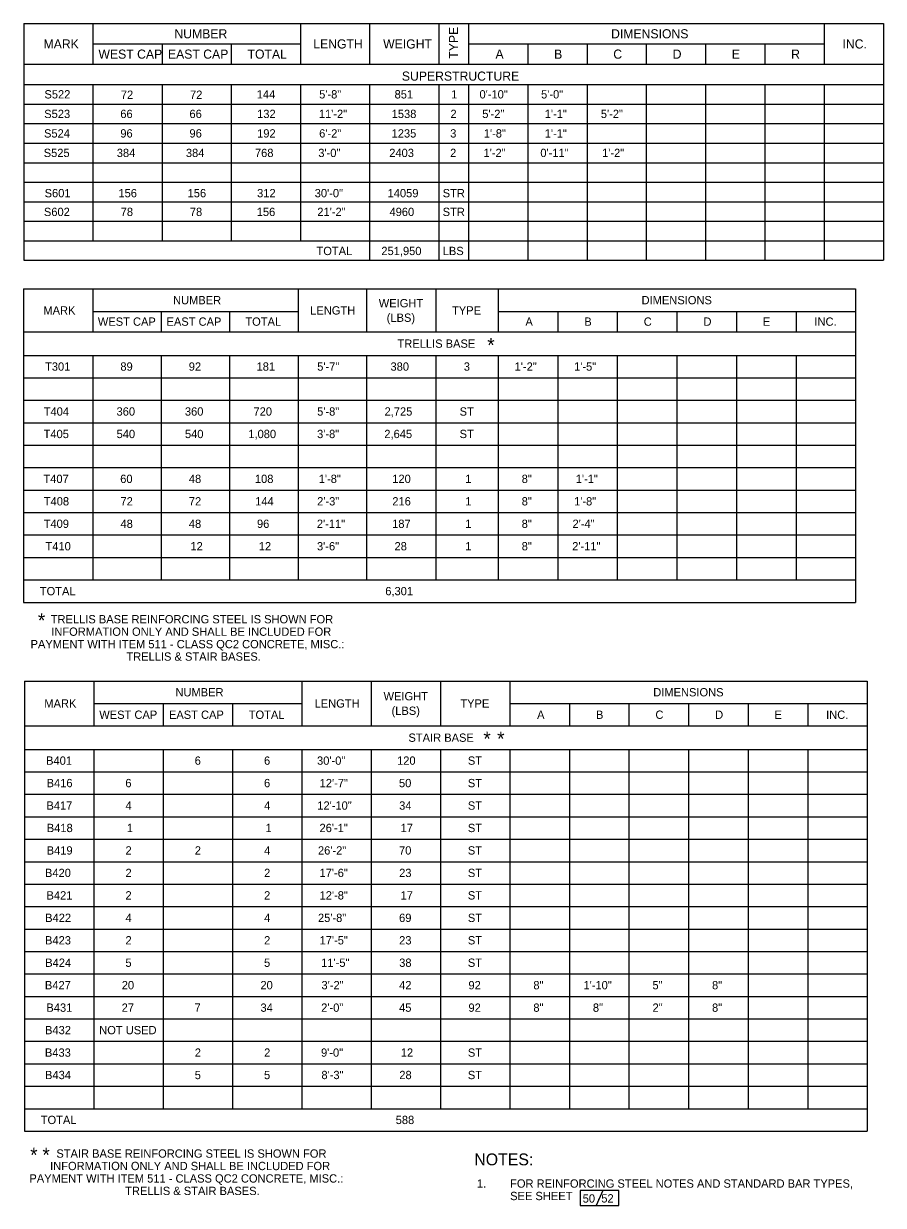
# Model space of a CAD drawing. Extents: x -47.5 to 51.5, y 0.9 to 23.7.
# Drawn here: x -32.4 to -17.9, y 0.94 to 20.88 of the extents above; entities that cross this region are included whole.
import ezdxf

# ---------------------------------------------------------------- set-up
doc = ezdxf.new("R2010")
doc.units = 0
for name, color, linetype in [('BR_P_Gen_Text', 7, 'Continuous'), ('BR_X_Slab_Const_Joint', 7, 'Continuous'), ('BR_X_Slab_Object', 7, 'Continuous')]:
    doc.layers.add(name, color=color, linetype=linetype)

msp = doc.modelspace()

# ---------------------------------------------------------------- linework, layer by layer
at = {"layer": 'BR_X_Slab_Const_Joint'}
for p, q in [((-32.399, 20.878), (-32.399, 16.886)), ((-32.399, 20.878), (-17.898, 20.878)), ((-31.232, 20.878), (-31.232, 20.193)), ((-27.732, 20.878), (-27.732, 20.193)), ((-26.565, 20.878), (-26.565, 20.193)), ((-25.398, 20.878), (-25.398, 20.193)), ((-24.898, 20.878), (-24.898, 20.193)), ((-18.898, 20.878), (-18.898, 20.193)), ((-17.898, 20.878), (-17.898, 16.886)), ((-31.232, 20.536), (-27.732, 20.536)), ((-30.065, 20.536), (-30.065, 20.193)), ((-28.899, 20.536), (-28.899, 20.193)), ((-24.898, 20.536), (-18.898, 20.536)), ((-23.898, 20.536), (-23.898, 20.193)), ((-22.897, 20.536), (-22.897, 20.193)), ((-21.901, 20.536), (-21.901, 20.193)), ((-20.898, 20.536), (-20.898, 20.193)), ((-19.898, 20.536), (-19.898, 20.193)), ((-32.399, 20.322), (-32.399, 19.057)), ((-32.399, 20.193), (-17.898, 20.193)), ((-32.399, 19.851), (-17.898, 19.851)), ((-31.232, 19.851), (-31.232, 17.215)), ((-30.065, 19.851), (-30.065, 17.215)), ((-28.899, 19.851), (-28.899, 17.215)), ((-27.732, 19.851), (-27.732, 17.215)), ((-26.565, 19.851), (-26.565, 16.886)), ((-25.398, 19.851), (-25.398, 16.886)), ((-24.898, 19.851), (-24.898, 16.886)), ((-23.898, 19.851), (-23.898, 16.886)), ((-22.897, 19.851), (-22.897, 16.886)), ((-21.901, 19.851), (-21.901, 16.886)), ((-20.898, 19.851), (-20.898, 16.886)), ((-19.898, 19.851), (-19.898, 16.886)), ((-18.898, 19.851), (-18.898, 16.886)), ((-32.399, 19.521), (-17.898, 19.521)), ((-32.399, 19.192), (-17.898, 19.192)), ((-32.399, 18.862), (-17.898, 18.862)), ((-32.399, 18.533), (-17.898, 18.533)), ((-32.399, 18.203), (-17.898, 18.203)), ((-32.399, 17.874), (-17.898, 17.874)), ((-32.399, 17.545), (-17.898, 17.545)), ((-32.399, 17.215), (-17.898, 17.215)), ((-32.399, 16.886), (-17.898, 16.886)), ((-32.399, 16.886), (-17.898, 16.886)), ((-32.399, 16.886), (-17.898, 16.886)), ((-32.399, 16.886), (-17.898, 16.886)), ((-32.399, 16.886), (-17.898, 16.886)), ((-32.399, 16.886), (-17.898, 16.886)), ((-32.399, 16.886), (-17.898, 16.886)), ((-22.628, 1.195), (-22.743, 0.945))]:
    msp.add_line(p, q, dxfattribs=at)
msp.add_lwpolyline([(-23.01, 0.945), (-22.36, 0.945), (-22.36, 1.195), (-23.01, 1.195)], close=True, dxfattribs=at)
at = {"layer": 'BR_X_Slab_Object'}
for p, q in [((-32.4, 16.403), (-18.367, 16.403)), ((-32.4, 16.403), (-32.4, 11.116)), ((-31.231, 16.403), (-31.231, 15.679)), ((-27.772, 16.403), (-27.772, 15.679)), ((-26.619, 16.403), (-26.619, 15.679)), ((-25.449, 16.403), (-25.449, 15.679)), ((-24.395, 16.403), (-24.395, 15.679)), ((-18.367, 16.403), (-18.367, 11.116)), ((-31.231, 16.025), (-27.772, 16.025)), ((-30.078, 16.025), (-30.078, 15.679)), ((-28.925, 16.025), (-28.925, 15.679)), ((-24.395, 16.025), (-18.367, 16.025)), ((-23.391, 16.025), (-23.391, 15.679)), ((-22.386, 16.025), (-22.386, 15.679)), ((-21.381, 16.025), (-21.381, 15.679)), ((-20.376, 16.025), (-20.376, 15.679)), ((-19.372, 16.025), (-19.372, 15.679)), ((-32.4, 15.679), (-18.367, 15.679)), ((-32.4, 15.283), (-18.367, 15.283)), ((-31.231, 15.283), (-31.231, 11.495)), ((-30.078, 15.283), (-30.078, 11.495)), ((-28.925, 15.283), (-28.925, 11.495)), ((-27.772, 15.283), (-27.772, 11.495)), ((-26.619, 15.283), (-26.619, 11.495)), ((-25.449, 15.283), (-25.449, 11.495)), ((-24.395, 15.283), (-24.395, 11.495)), ((-23.391, 15.283), (-23.391, 11.495)), ((-22.386, 15.283), (-22.386, 11.495)), ((-21.381, 15.283), (-21.381, 11.495)), ((-20.376, 15.283), (-20.376, 11.495)), ((-19.372, 15.283), (-19.372, 11.495)), ((-32.4, 14.905), (-18.367, 14.905)), ((-32.4, 14.526), (-18.367, 14.526)), ((-32.4, 14.147), (-18.367, 14.147)), ((-32.4, 13.768), (-18.367, 13.768)), ((-32.4, 13.389), (-18.367, 13.389)), ((-32.4, 13.01), (-18.367, 13.01)), ((-32.4, 12.632), (-18.367, 12.632)), ((-32.4, 12.253), (-18.367, 12.253)), ((-32.4, 11.874), (-18.367, 11.874)), ((-32.4, 11.495), (-18.367, 11.495)), ((-32.4, 11.116), (-18.367, 11.116)), ((-32.384, 9.789), (-18.17, 9.789)), ((-32.384, 9.789), (-32.384, 2.196)), ((-31.215, 9.789), (-31.215, 9.032)), ((-27.706, 9.789), (-27.706, 9.032)), ((-26.537, 9.789), (-26.537, 9.032)), ((-25.368, 9.789), (-25.368, 9.032)), ((-24.198, 9.789), (-24.198, 9.032)), ((-18.17, 9.789), (-18.17, 2.196)), ((-31.215, 9.411), (-27.706, 9.411)), ((-30.045, 9.411), (-30.045, 9.032)), ((-28.876, 9.411), (-28.876, 9.032)), ((-24.198, 9.411), (-18.17, 9.411)), ((-23.194, 9.411), (-23.194, 9.032)), ((-22.189, 9.411), (-22.189, 9.032)), ((-21.184, 9.411), (-21.184, 9.032)), ((-20.179, 9.411), (-20.179, 9.032)), ((-19.175, 9.411), (-19.175, 9.032)), ((-32.384, 9.032), (-18.17, 9.032)), ((-32.384, 8.636), (-18.17, 8.636)), ((-31.215, 8.636), (-31.215, 2.575)), ((-30.045, 8.636), (-30.045, 2.575)), ((-28.876, 8.636), (-28.876, 2.575)), ((-27.706, 8.636), (-27.706, 2.575)), ((-26.537, 8.636), (-26.537, 2.575)), ((-25.368, 8.636), (-25.368, 2.575)), ((-24.198, 8.636), (-24.198, 2.575)), ((-23.194, 8.636), (-23.194, 2.575)), ((-22.189, 8.636), (-22.189, 2.575)), ((-21.184, 8.636), (-21.184, 2.575)), ((-20.179, 8.636), (-20.179, 2.575)), ((-19.175, 8.636), (-19.175, 2.575)), ((-32.384, 8.258), (-18.17, 8.258)), ((-32.384, 7.879), (-18.17, 7.879)), ((-32.384, 7.5), (-18.17, 7.5)), ((-32.384, 7.121), (-18.17, 7.121)), ((-32.384, 6.742), (-18.17, 6.742)), ((-32.384, 6.364), (-18.17, 6.364)), ((-32.384, 5.985), (-18.17, 5.985)), ((-32.384, 5.606), (-18.17, 5.606)), ((-32.384, 5.227), (-18.17, 5.227)), ((-32.384, 4.848), (-18.17, 4.848)), ((-32.384, 4.469), (-18.17, 4.469)), ((-32.384, 4.091), (-18.17, 4.091)), ((-32.384, 3.712), (-18.17, 3.712)), ((-32.384, 3.333), (-18.17, 3.333)), ((-32.384, 2.954), (-18.17, 2.954)), ((-32.384, 2.575), (-18.17, 2.575)), ((-32.384, 2.196), (-18.17, 2.196))]:
    msp.add_line(p, q, dxfattribs=at)

# ---------------------------------------------------------------- texts
at = {"layer": 'BR_P_Gen_Text'}
for s, p in [('NUMBER', (-29.88, 16.144)), ('WEIGHT', (-26.41, 16.093)), ('DIMENSIONS', (-21.977, 16.144)), ('MARK', (-32.067, 15.971)), ('LENGTH', (-27.566, 15.971)), ('(LBS)', (-26.276, 15.848)), ('TYPE', (-25.174, 15.971)), ('WEST CAP', (-31.148, 15.782)), ('EAST CAP', (-29.99, 15.782)), ('TOTAL', (-28.66, 15.782)), ('A', (-23.936, 15.782)), ('B', (-22.943, 15.782)), ('C', (-21.94, 15.782)), ('D', (-20.933, 15.782)), ('E', (-19.931, 15.782)), ('INC.', (-19.061, 15.782)), ('TRELLIS BASE', (-26.093, 15.411)), ('T301', (-32.039, 15.024)), ('89', (-30.768, 15.024)), ('92', (-29.615, 15.024)), ('181', (-28.471, 15.024)), ('5\'-7"', (-27.448, 15.024)), ('380', (-26.212, 15.024)), ('3', (-24.976, 15.024)), ('1\'-2"', (-24.118, 15.024)), ('1\'-5"', (-23.115, 15.024)), ('T404', (-32.061, 14.266)), ('360', (-30.833, 14.266)), ('360', (-29.68, 14.266)), ('720', (-28.523, 14.266)), ('5\'-8"', (-27.449, 14.266)), ('2,725', (-26.312, 14.266)), ('ST', (-25.046, 14.266)), ('T405', (-32.063, 13.887)), ('540', (-30.832, 13.887)), ('540', (-29.679, 13.887)), ('1,080', (-28.61, 13.887)), ('3\'-8"', (-27.45, 13.887)), ('2,645', (-26.316, 13.887)), ('ST', (-25.046, 13.887)), ('T407', (-32.066, 13.13)), ('60', (-30.771, 13.13)), ('48', (-29.613, 13.13)), ('108', (-28.499, 13.13)), ('1\'-8"', (-27.422, 13.13)), ('120', (-26.182, 13.13)), ('1', (-24.951, 13.13)), ('8"', (-23.999, 13.13)), ('1\'-1"', (-23.087, 13.13)), ('T408', (-32.06, 12.751)), ('72', (-30.766, 12.751)), ('72', (-29.613, 12.751)), ('144', (-28.494, 12.751)), ('2\'-3"', (-27.449, 12.751)), ('216', (-26.181, 12.751)), ('1', (-24.951, 12.751)), ('8"', (-23.999, 12.751)), ('1\'-8"', (-23.115, 12.751)), ('T409', (-32.062, 12.372)), ('48', (-30.766, 12.372)), ('48', (-29.613, 12.372)), ('96', (-28.464, 12.372)), ('2\'-11"', (-27.454, 12.372)), ('187', (-26.184, 12.372)), ('1', (-24.951, 12.372)), ('8"', (-23.999, 12.372)), ('2\'-4"', (-23.142, 12.372)), ('T410', (-32.031, 11.993)), ('12', (-29.587, 11.993)), ('12', (-28.434, 11.993)), ('3\'-6"', (-27.452, 11.993)), ('28', (-26.144, 11.993)), ('1', (-24.951, 11.993)), ('8"', (-23.999, 11.993)), ('2\'-11"', (-23.147, 11.993)), ('TOTAL', (-32.127, 11.236)), ('6,301', (-26.3, 11.236)), ('NUMBER', (-29.839, 9.53)), ('WEIGHT', (-26.329, 9.463)), ('DIMENSIONS', (-21.78, 9.53)), ('MARK', (-32.051, 9.341)), ('LENGTH', (-27.492, 9.341)), ('TYPE', (-25.034, 9.341)), ('WEST CAP', (-31.124, 9.151)), ('EAST CAP', (-29.949, 9.151)), ('TOTAL', (-28.603, 9.151)), ('(LBS)', (-26.194, 9.218)), ('A', (-23.739, 9.151)), ('B', (-22.746, 9.151)), ('C', (-21.743, 9.151)), ('D', (-20.736, 9.151)), ('E', (-19.734, 9.151)), ('INC.', (-18.864, 9.151)), ('STAIR BASE ', (-25.909, 8.764)), ('B401', (-32.021, 8.377)), ('6', (-29.515, 8.377)), ('6', (-28.345, 8.377)), ('30\'-0"', (-27.451, 8.377)), ('120', (-26.101, 8.377)), ('ST', (-24.907, 8.377)), ('B416', (-32.012, 7.998)), ('6', (-30.684, 7.998)), ('6', (-28.345, 7.998)), ('12\'-7"', (-27.407, 7.998)), ('50', (-26.069, 7.998)), ('ST', (-24.907, 7.998)), ('B417', (-32.015, 7.619)), ('4', (-30.682, 7.619)), ('4', (-28.343, 7.619)), ('12\'-10"', (-27.447, 7.619)), ('34', (-26.066, 7.619)), ('ST', (-24.907, 7.619)), ('B418', (-32.009, 7.241)), ('1', (-30.659, 7.241)), ('1', (-28.32, 7.241)), ('26\'-1"', (-27.409, 7.241)), ('17', (-26.042, 7.241)), ('ST', (-24.907, 7.241)), ('B419', (-32.011, 6.862)), ('2', (-30.682, 6.862)), ('2', (-29.513, 6.862)), ('4', (-28.343, 6.862)), ('26\'-2"', (-27.435, 6.862)), ('70', (-26.068, 6.862)), ('ST', (-24.907, 6.862)), ('B420', (-32.04, 6.483)), ('2', (-30.682, 6.483)), ('2', (-28.344, 6.483)), ('17\'-6"', (-27.409, 6.483)), ('23', (-26.066, 6.483)), ('ST', (-24.907, 6.483)), ('B421', (-32.014, 6.104)), ('2', (-30.682, 6.104)), ('2', (-28.344, 6.104)), ('12\'-8"', (-27.408, 6.104)), ('17', (-26.042, 6.104)), ('ST', (-24.907, 6.104)), ('B422', (-32.037, 5.725)), ('4', (-30.682, 5.725)), ('4', (-28.343, 5.725)), ('25\'-8"', (-27.435, 5.725)), ('69', (-26.067, 5.725)), ('ST', (-24.907, 5.725)), ('B423', (-32.039, 5.346)), ('2', (-30.682, 5.346)), ('2', (-28.344, 5.346)), ('17\'-5"', (-27.408, 5.346)), ('23', (-26.066, 5.346)), ('ST', (-24.907, 5.346)), ('B424', (-32.036, 4.968)), ('5', (-30.683, 4.968)), ('5', (-28.345, 4.968)), ('11\'-5"', (-27.381, 4.968)), ('38', (-26.065, 4.968)), ('ST', (-24.907, 4.968)), ('B427', (-32.041, 4.589)), ('20', (-30.745, 4.589)), ('20', (-28.406, 4.589)), ('3\'-2"', (-27.376, 4.589)), ('42', (-26.066, 4.589)), ('92', (-24.897, 4.589)), ('8"', (-23.802, 4.589)), ('1\'-10"', (-22.957, 4.589)), ('5"', (-21.793, 4.589)), ('8"', (-20.788, 4.589)), ('B431', (-32.016, 4.21)), ('27', (-30.746, 4.21)), ('7', (-29.517, 4.21)), ('34', (-28.405, 4.21)), ('2\'-0"', (-27.381, 4.21)), ('45', (-26.067, 4.21)), ('92', (-24.897, 4.21)), ('8"', (-23.802, 4.21)), ('8"', (-22.798, 4.21)), ('2"', (-21.792, 4.21)), ('8"', (-20.788, 4.21)), ('B432', (-32.039, 3.831)), ('NOT USED', (-31.125, 3.831)), ('B433', (-32.041, 3.452)), ('2', (-29.513, 3.452)), ('2', (-28.344, 3.452)), ('9\'-0"', (-27.384, 3.452)), ('12', (-26.038, 3.452)), ('ST', (-24.907, 3.452)), ('B434', (-32.039, 3.074)), ('5', (-29.514, 3.074)), ('5', (-28.345, 3.074)), ('8\'-3"', (-27.377, 3.074)), ('28', (-26.063, 3.074)), ('ST', (-24.907, 3.074)), ('TOTAL', (-32.111, 2.316)), ('588', (-26.124, 2.316)), ('50', (-22.97, 0.991)), ('52', (-22.656, 0.993))]:
    msp.add_text(s, height=0.14, dxfattribs=at).set_placement(p)
at = {"layer": 'BR_X_Slab_Const_Joint'}
for s, height, p in [('NUMBER', 0.154, (-29.857, 20.63)), ('DIMENSIONS', 0.154, (-22.491, 20.63)), ('MARK', 0.154, (-32.064, 20.459)), ('LENGTH', 0.154, (-27.515, 20.459)), ('WEIGHT', 0.154, (-26.336, 20.459)), ('INC.', 0.154, (-18.588, 20.459)), ('WEST CAP', 0.154, (-31.138, 20.287)), ('EAST CAP', 0.154, (-29.966, 20.287)), ('TOTAL', 0.154, (-28.623, 20.287)), ('A', 0.154, (-24.441, 20.287)), ('B', 0.154, (-23.452, 20.287)), ('C', 0.154, (-22.454, 20.287)), ('D', 0.154, (-21.452, 20.287)), ('E', 0.154, (-20.455, 20.287)), ('R', 0.154, (-19.454, 20.287)), ('SUPERSTRUCTURE', 0.154, (-26.02, 19.916)), ('S522', 0.14, (-32.049, 19.616)), ('72', 0.14, (-30.76, 19.609)), ('72', 0.14, (-29.594, 19.609)), ('144', 0.14, (-28.468, 19.616)), ('5\'-8"', 0.14, (-27.415, 19.616)), ('851', 0.14, (-26.143, 19.616)), ('1', 0.14, (-25.188, 19.616)), ('0\'-10"', 0.14, (-24.711, 19.616)), ('5\'-0"', 0.14, (-23.672, 19.616)), ('S523', 0.14, (-32.053, 19.286)), ('66', 0.14, (-30.769, 19.286)), ('66', 0.14, (-29.603, 19.286)), ('132', 0.14, (-28.462, 19.286)), ('11\'-2"', 0.14, (-27.42, 19.286)), ('1538', 0.14, (-26.192, 19.286)), ('2', 0.14, (-25.201, 19.286)), ('5\'-2"', 0.14, (-24.664, 19.286)), ('1\'-1"', 0.14, (-23.61, 19.286)), ('5\'-2"', 0.14, (-22.664, 19.286)), ('S524', 0.14, (-32.056, 18.957)), ('96', 0.14, (-30.769, 18.957)), ('96', 0.14, (-29.603, 18.957)), ('192', 0.14, (-28.462, 18.957)), ('6\'-2"', 0.14, (-27.415, 18.957)), ('1235', 0.14, (-26.193, 18.957)), ('3', 0.14, (-25.205, 18.957)), ('1\'-8"', 0.14, (-24.638, 18.957)), ('1\'-1"', 0.14, (-23.61, 18.957)), ('S525', 0.14, (-32.061, 18.628)), ('384', 0.14, (-30.829, 18.628)), ('384', 0.14, (-29.663, 18.628)), ('768', 0.14, (-28.498, 18.628)), ('3\'-0"', 0.14, (-27.43, 18.628)), ('2403', 0.14, (-26.233, 18.628)), ('2', 0.14, (-25.207, 18.628)), ('1\'-2"', 0.14, (-24.643, 18.628)), ('0\'-11"', 0.14, (-23.684, 18.628)), ('1\'-2"', 0.14, (-22.643, 18.628)), ('S601', 0.14, (-32.046, 17.949)), ('156', 0.14, (-30.801, 17.949)), ('156', 0.14, (-29.634, 17.949)), ('312', 0.14, (-28.462, 17.949)), ('30\'-0"', 0.14, (-27.49, 17.949)), ('14059', 0.14, (-26.261, 17.949)), ('STR', 0.14, (-25.332, 17.949)), ('S602', 0.14, (-32.058, 17.633)), ('78', 0.14, (-30.763, 17.633)), ('78', 0.14, (-29.596, 17.633)), ('156', 0.14, (-28.468, 17.633)), ('21\'-2"', 0.14, (-27.446, 17.633)), ('4960', 0.14, (-26.229, 17.633)), ('STR', 0.14, (-25.332, 17.633)), ('TOTAL', 0.14, (-27.46, 16.974)), ('251,950', 0.14, (-26.366, 16.974)), ('LBS', 0.14, (-25.331, 16.974)), ('*', 0.24, (-24.58, 15.336)), ('*', 0.24, (-32.16, 10.692)), ('TRELLIS BASE REINFORCING STEEL IS SHOWN FOR', 0.14, (-31.943, 10.762)), ('INFORMATION ONLY AND SHALL BE INCLUDED FOR ', 0.14, (-31.934, 10.552)), ('PAYMENT WITH ITEM 511 - CLASS QC2 CONCRETE, MISC.:', 0.14, (-32.283, 10.342)), ('TRELLIS & STAIR BASES.', 0.14, (-30.667, 10.132)), ('*', 0.24, (-24.645, 8.696)), ('*', 0.24, (-24.414, 8.696)), ('*', 0.24, (-32.29, 1.676)), ('*', 0.24, (-32.083, 1.676)), ('STAIR BASE REINFORCING STEEL IS SHOWN FOR ', 0.14, (-31.848, 1.749)), ('NOTES:', 0.2, (-24.798, 1.62)), ('INFORMATION ONLY AND SHALL BE INCLUDED FOR ', 0.14, (-31.953, 1.539)), ('PAYMENT WITH ITEM 511 - CLASS QC2 CONCRETE, MISC.:', 0.14, (-32.303, 1.329)), ('TRELLIS & STAIR BASES.', 0.14, (-30.687, 1.119)), ('1.', 0.14, (-24.754, 1.243)), ('1.', 0.14, (-24.754, 1.243)), ('FOR REINFORCING STEEL NOTES AND STANDARD BAR TYPES, ', 0.14, (-24.194, 1.243)), ('FOR REINFORCING STEEL NOTES AND STANDARD BAR TYPES, ', 0.14, (-24.194, 1.243)), ('SEE SHEET        .', 0.14, (-24.194, 1.033)), ('SEE SHEET        .', 0.14, (-24.194, 1.033))]:
    msp.add_text(s, height=height, dxfattribs=at).set_placement(p)
msp.add_text('TYPE', height=0.154, rotation=90, dxfattribs=at).set_placement((-25.071, 20.287))

doc.saveas('drawing.dxf')
